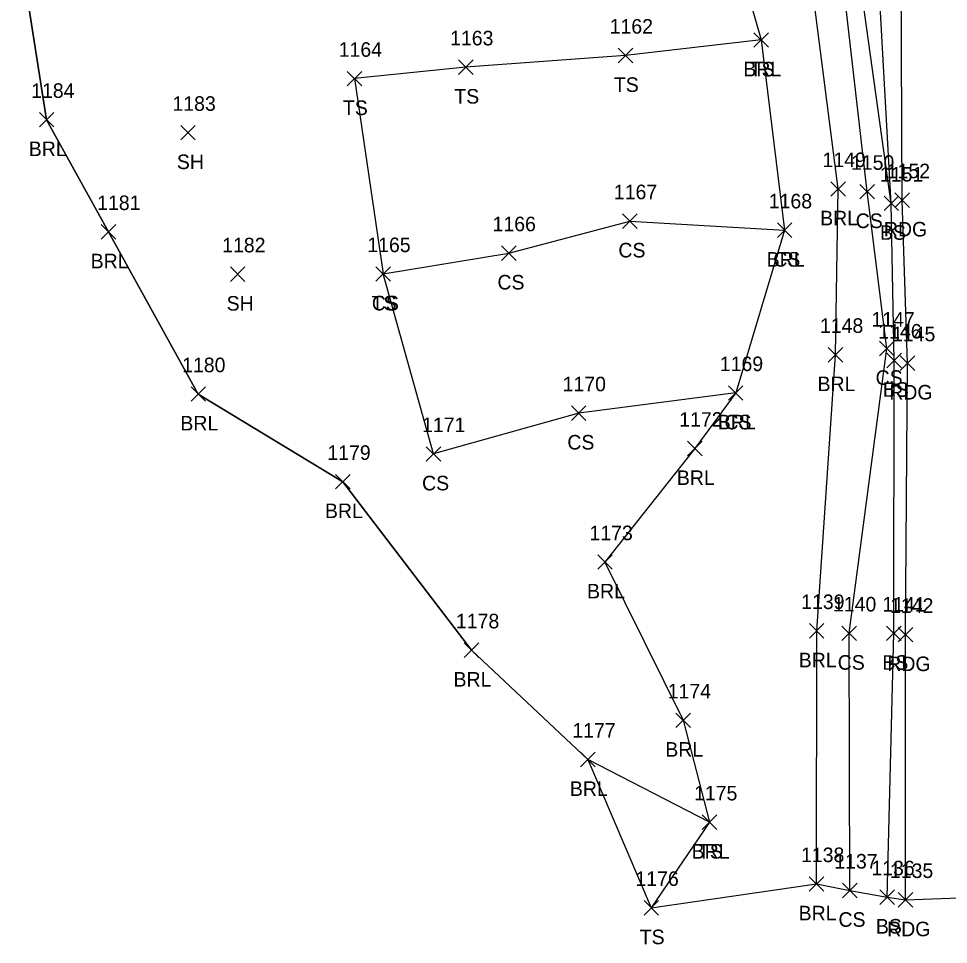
# Model space of a CAD drawing. Extents: x 1459992 to 1461532, y 647785 to 648535.
# Drawn here: x 1461268.7 to 1461396.4, y 647795.2 to 647922.3 of the extents above; entities that cross this region are included whole.
import ezdxf

# ---------------------------------------------------------------- set-up
doc = ezdxf.new("R2010")
doc.units = 0
for name, color, linetype in [('L_A', 7, 'Continuous'), ('L_I', 7, 'Continuous'), ('L_TIC', 7, 'Continuous'), ('LABL', 7, 'Continuous'), ('LELB', 7, 'Continuous'), ('LSOGP', 7, 'Continuous'), ('P_A', 7, 'Continuous'), ('P_I', 7, 'Continuous'), ('P_TIC', 7, 'Continuous'), ('PEU', 7, 'Continuous')]:
    doc.layers.add(name, color=color, linetype=linetype)

msp = doc.modelspace()

# ---------------------------------------------------------------- linework, layer by layer
at = {"layer": 'L_TIC'}
for points in [[(1461369.71, 647918.4), (1461371.71, 647920.4)], [(1461371.71, 647918.4), (1461369.71, 647920.4)], [(1461369.71, 647918.4), (1461371.71, 647920.4)], [(1461371.71, 647918.4), (1461369.71, 647920.4)], [(1461351.06, 647916.27), (1461353.06, 647918.27)], [(1461353.06, 647916.27), (1461351.06, 647918.27)], [(1461329.15, 647914.66), (1461331.15, 647916.66)], [(1461331.15, 647914.66), (1461329.15, 647916.66)], [(1461313.86, 647913.09), (1461315.86, 647915.09)], [(1461315.86, 647913.09), (1461313.86, 647915.09)], [(1461271.57, 647907.45), (1461273.57, 647909.45)], [(1461273.57, 647907.45), (1461271.57, 647909.45)], [(1461290.98, 647905.67), (1461292.98, 647907.67)], [(1461292.98, 647905.67), (1461290.98, 647907.67)], [(1461380.26, 647897.94), (1461382.26, 647899.94)], [(1461382.26, 647897.94), (1461380.26, 647899.94)], [(1461384.24, 647897.57), (1461386.24, 647899.57)], [(1461386.24, 647897.57), (1461384.24, 647899.57)], [(1461387.57, 647895.96), (1461389.57, 647897.96)], [(1461389.57, 647895.96), (1461387.57, 647897.96)], [(1461387.57, 647895.96), (1461389.57, 647897.96)], [(1461389.57, 647895.96), (1461387.57, 647897.96)], [(1461351.65, 647893.53), (1461353.65, 647895.53)], [(1461353.65, 647893.53), (1461351.65, 647895.53)], [(1461372.92, 647892.27), (1461374.92, 647894.27)], [(1461374.92, 647892.27), (1461372.92, 647894.27)], [(1461372.92, 647892.27), (1461374.92, 647894.27)], [(1461374.92, 647892.27), (1461372.92, 647894.27)], [(1461280.07, 647892.04), (1461282.07, 647894.04)], [(1461282.07, 647892.04), (1461280.07, 647894.04)], [(1461335.04, 647889.13), (1461337.04, 647891.13)], [(1461337.04, 647889.13), (1461335.04, 647891.13)], [(1461297.8, 647886.23), (1461299.8, 647888.23)], [(1461299.8, 647886.23), (1461297.8, 647888.23)], [(1461317.79, 647886.26), (1461319.79, 647888.26)], [(1461319.79, 647886.26), (1461317.79, 647888.26)], [(1461317.79, 647886.26), (1461319.79, 647888.26)], [(1461319.79, 647886.26), (1461317.79, 647888.26)], [(1461386.97, 647876.03), (1461388.97, 647878.03)], [(1461388.97, 647876.03), (1461386.97, 647878.03)], [(1461379.9, 647875.17), (1461381.9, 647877.17)], [(1461381.9, 647875.17), (1461379.9, 647877.17)], [(1461387.96, 647874.39), (1461389.96, 647876.39)], [(1461389.96, 647874.39), (1461387.96, 647876.39)], [(1461292.4, 647869.77), (1461294.4, 647871.77)], [(1461294.4, 647869.77), (1461292.4, 647871.77)], [(1461366.2, 647869.92), (1461368.2, 647871.92)], [(1461368.2, 647869.92), (1461366.2, 647871.92)], [(1461366.2, 647869.92), (1461368.2, 647871.92)], [(1461368.2, 647869.92), (1461366.2, 647871.92)], [(1461344.64, 647867.15), (1461346.64, 647869.15)], [(1461346.64, 647867.15), (1461344.64, 647869.15)], [(1461360.58, 647862.28), (1461362.58, 647864.28)], [(1461362.58, 647862.28), (1461360.58, 647864.28)], [(1461324.69, 647861.54), (1461326.69, 647863.54)], [(1461326.69, 647861.54), (1461324.69, 647863.54)], [(1461312.25, 647857.73), (1461314.25, 647859.73)], [(1461314.25, 647857.73), (1461312.25, 647859.73)], [(1461348.25, 647846.7), (1461350.25, 647848.7)], [(1461350.25, 647846.7), (1461348.25, 647848.7)], [(1461377.32, 647837.24), (1461379.32, 647839.24)], [(1461379.32, 647837.24), (1461377.32, 647839.24)], [(1461381.77, 647836.91), (1461383.77, 647838.91)], [(1461383.77, 647836.91), (1461381.77, 647838.91)], [(1461387.9, 647836.9), (1461389.9, 647838.9)], [(1461389.9, 647836.9), (1461387.9, 647838.9)], [(1461329.91, 647834.59), (1461331.91, 647836.59)], [(1461331.91, 647834.59), (1461329.91, 647836.59)], [(1461358.99, 647824.96), (1461360.99, 647826.96)], [(1461360.99, 647824.96), (1461358.99, 647826.96)], [(1461345.89, 647819.57), (1461347.89, 647821.57)], [(1461347.89, 647819.57), (1461345.89, 647821.57)], [(1461362.61, 647810.96), (1461364.61, 647812.96)], [(1461364.61, 647810.96), (1461362.61, 647812.96)], [(1461362.61, 647810.96), (1461364.61, 647812.96)], [(1461364.61, 647810.96), (1461362.61, 647812.96)], [(1461377.29, 647802.48), (1461379.29, 647804.48)], [(1461379.29, 647802.48), (1461377.29, 647804.48)], [(1461381.87, 647801.6), (1461383.87, 647803.6)], [(1461383.87, 647801.6), (1461381.87, 647803.6)], [(1461387.01, 647800.67), (1461389.01, 647802.67)], [(1461389.01, 647800.67), (1461387.01, 647802.67)], [(1461354.61, 647799.21), (1461356.61, 647801.21)], [(1461356.61, 647799.21), (1461354.61, 647801.21)]]:
    msp.add_lwpolyline(points, dxfattribs=at)
at = {"layer": 'LABL'}
msp.add_lwpolyline([(1461378.29, 647803.48), (1461378.32, 647838.24), (1461380.9, 647876.17), (1461381.26, 647898.94), (1461377.32, 647929.66), (1461367.57, 647930.25), (1461370.71, 647919.4), (1461373.92, 647893.27), (1461367.2, 647870.92), (1461361.58, 647863.28), (1461349.25, 647847.7), (1461359.99, 647825.96), (1461363.61, 647811.96), (1461346.89, 647820.57), (1461330.91, 647835.59), (1461313.25, 647858.73), (1461293.4, 647870.77), (1461281.07, 647893.04), (1461272.57, 647908.45), (1461268.72, 647933.04)], dxfattribs=at)
at = {"layer": 'LELB'}
for points in [[(1461388.01, 647801.67), (1461388.9, 647837.9), (1461388.96, 647875.39), (1461388.57, 647896.96), (1461386.79, 647928.22), (1461384.47, 647961.49), (1461379.85, 647993.2), (1461373.75, 648023.7)], [(1461382.87, 647802.6), (1461382.77, 647837.91), (1461387.97, 647877.03), (1461385.24, 647898.57), (1461381.84, 647928.53), (1461377.17, 647960.46), (1461376.93, 647993.4), (1461373.75, 648023.7)], [(1461388.57, 647896.96), (1461384.16, 647928.51), (1461381.16, 647960.91), (1461379.85, 647993.2)], [(1461370.71, 647919.4), (1461352.06, 647917.27), (1461330.15, 647915.66), (1461314.86, 647914.09), (1461318.79, 647887.26)], [(1461318.79, 647887.26), (1461336.04, 647890.13), (1461352.65, 647894.53), (1461373.92, 647893.27)], [(1461325.69, 647862.54), (1461318.79, 647887.26)], [(1461367.2, 647870.92), (1461345.64, 647868.15), (1461325.69, 647862.54)], [(1461363.61, 647811.96), (1461355.61, 647800.21)]]:
    msp.add_lwpolyline(points, dxfattribs=at)
at = {"layer": 'LSOGP'}
msp.add_lwpolyline([(1461268.72, 647933.04), (1461272.57, 647908.45), (1461281.07, 647893.04), (1461293.4, 647870.77), (1461313.25, 647858.73), (1461330.91, 647835.59), (1461346.89, 647820.57), (1461355.61, 647800.21), (1461378.29, 647803.48), (1461382.87, 647802.6), (1461388.01, 647801.67), (1461390.51, 647801.3), (1461399.1, 647801.61)], dxfattribs=at)
at = {"layer": 'P_TIC'}
for points in [[(1461389.06, 647896.41), (1461391.06, 647898.41)], [(1461391.06, 647896.41), (1461389.06, 647898.41)], [(1461389.8, 647874.02), (1461391.8, 647876.02)], [(1461391.8, 647874.02), (1461389.8, 647876.02)], [(1461389.53, 647836.72), (1461391.53, 647838.72)], [(1461391.53, 647836.72), (1461389.53, 647838.72)], [(1461389.51, 647800.3), (1461391.51, 647802.3)], [(1461391.51, 647800.3), (1461389.51, 647802.3)]]:
    msp.add_lwpolyline(points, dxfattribs=at)
at = {"layer": 'PEU'}
msp.add_lwpolyline([(1461390.51, 647801.3), (1461390.53, 647837.72), (1461390.8, 647875.02), (1461390.06, 647897.41), (1461389.91, 647928.52), (1461386.45, 647961.52), (1461383.38, 647992.89), (1461381.21, 648024), (1461378.9, 648057), (1461379.85, 648065.17), (1461378.22, 648080.01), (1461375.84, 648101.64), (1461371.39, 648120.78), (1461367.19, 648133.39), (1461361.39, 648144.72), (1461357.89, 648149.47), (1461353.74, 648153.76)], dxfattribs=at)

# ---------------------------------------------------------------- texts
at = {"layer": 'L_A'}
for s, p in [('BRL', (1461368.25, 647914.4)), ('TS', (1461369.12, 647914.4)), ('TS', (1461350.47, 647912.27)), ('TS', (1461328.56, 647910.66)), ('TS', (1461313.26, 647909.09)), ('BRL', (1461270.12, 647903.45)), ('SH', (1461290.46, 647901.67)), ('BRL', (1461378.8, 647893.94)), ('CS', (1461383.68, 647893.57)), ('BS', (1461387.01, 647891.96)), ('BS', (1461387.01, 647891.96)), ('CS', (1461351.09, 647889.53)), ('BRL', (1461278.62, 647888.04)), ('BRL', (1461371.46, 647888.27)), ('CS', (1461372.36, 647888.27)), ('CS', (1461334.48, 647885.13)), ('SH', (1461297.29, 647882.23)), ('TS', (1461317.2, 647882.26)), ('CS', (1461317.23, 647882.26)), ('CS', (1461386.41, 647872.03)), ('BRL', (1461378.44, 647871.17)), ('BS', (1461387.4, 647870.39)), ('BRL', (1461290.94, 647865.77)), ('BRL', (1461364.75, 647865.92)), ('CS', (1461365.65, 647865.92)), ('CS', (1461344.08, 647863.15)), ('BRL', (1461359.12, 647858.28)), ('CS', (1461324.13, 647857.54)), ('BRL', (1461310.79, 647853.73)), ('BRL', (1461346.79, 647842.7)), ('BRL', (1461375.86, 647833.24)), ('CS', (1461381.21, 647832.91)), ('BS', (1461387.34, 647832.9)), ('BRL', (1461328.45, 647830.59)), ('BRL', (1461357.53, 647820.96)), ('BRL', (1461344.43, 647815.57)), ('BRL', (1461361.15, 647806.96)), ('TS', (1461362.02, 647806.96)), ('BRL', (1461375.84, 647798.48)), ('CS', (1461381.31, 647797.6)), ('BS', (1461386.45, 647796.67)), ('TS', (1461354.02, 647795.21))]:
    msp.add_text(s, height=2, dxfattribs=at).set_placement(p)
at = {"layer": 'L_I'}
for s, p in [('1162', (1461349.89, 647920.27)), ('1163', (1461327.98, 647918.66)), ('1164', (1461312.68, 647917.09)), ('1184', (1461270.45, 647911.45)), ('1183', (1461289.85, 647909.67)), ('1149', (1461379.12, 647901.94)), ('1150', (1461383.03, 647901.57)), ('1151', (1461387.01, 647899.96)), ('1151', (1461387.01, 647899.96)), ('1167', (1461350.47, 647897.53)), ('1181', (1461279.51, 647896.04)), ('1168', (1461371.74, 647896.27)), ('1168', (1461371.74, 647896.27)), ('1166', (1461333.81, 647893.13)), ('1182', (1461296.68, 647890.23)), ('1165', (1461316.61, 647890.26)), ('1165', (1461316.61, 647890.26)), ('1147', (1461385.84, 647880.03)), ('1148', (1461378.77, 647879.17)), ('1146', (1461386.78, 647878.39)), ('1180', (1461291.18, 647873.77)), ('1169', (1461365.02, 647873.92)), ('1169', (1461365.02, 647873.92)), ('1170', (1461343.43, 647871.15)), ('1171', (1461324.13, 647865.54)), ('1172', (1461359.45, 647866.28)), ('1179', (1461311.12, 647861.73)), ('1173', (1461347.12, 647850.7)), ('1139', (1461376.19, 647841.24)), ('1140', (1461380.56, 647840.91)), ('1141', (1461387.34, 647840.9)), ('1178', (1461328.78, 647838.59)), ('1174', (1461357.86, 647828.96)), ('1177', (1461344.76, 647823.57)), ('1175', (1461361.48, 647814.96)), ('1175', (1461361.48, 647814.96)), ('1138', (1461376.17, 647806.48)), ('1137', (1461380.74, 647805.6)), ('1136', (1461385.83, 647804.67)), ('1176', (1461353.43, 647803.21))]:
    msp.add_text(s, height=2, dxfattribs=at).set_placement(p)
at = {"layer": 'P_A'}
for p in [(1461387.55, 647892.41), (1461388.29, 647870.02), (1461388.02, 647832.72), (1461387.99, 647796.3)]:
    msp.add_text('RDG', height=2, dxfattribs=at).set_placement(p)
at = {"layer": 'P_I'}
for s, p in [('1152', (1461387.94, 647900.41)), ('1145', (1461388.67, 647878.02)), ('1142', (1461388.4, 647840.72)), ('1135', (1461388.38, 647804.3))]:
    msp.add_text(s, height=2, dxfattribs=at).set_placement(p)

doc.saveas('drawing.dxf')
